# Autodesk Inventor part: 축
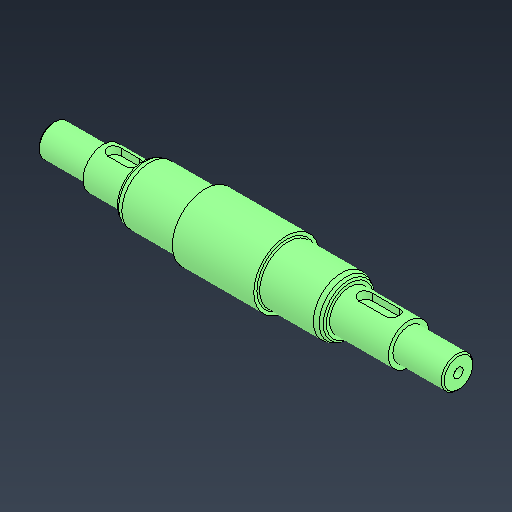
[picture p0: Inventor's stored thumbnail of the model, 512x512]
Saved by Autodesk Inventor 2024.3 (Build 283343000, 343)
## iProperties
Created: 2025-07
Part Number: 축
Material: 강철, 탄소
Document SubType Name: Modeling
Designer: user
Density: 7.85 g/cm^3
Appearance: 기본값
Sending System: Autodesk Inventor 2026
Preprocessor: ST-DEVELOPER v20.1
Author: jhkim
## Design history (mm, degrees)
feature "솔리드1"
node "솔리드2"
